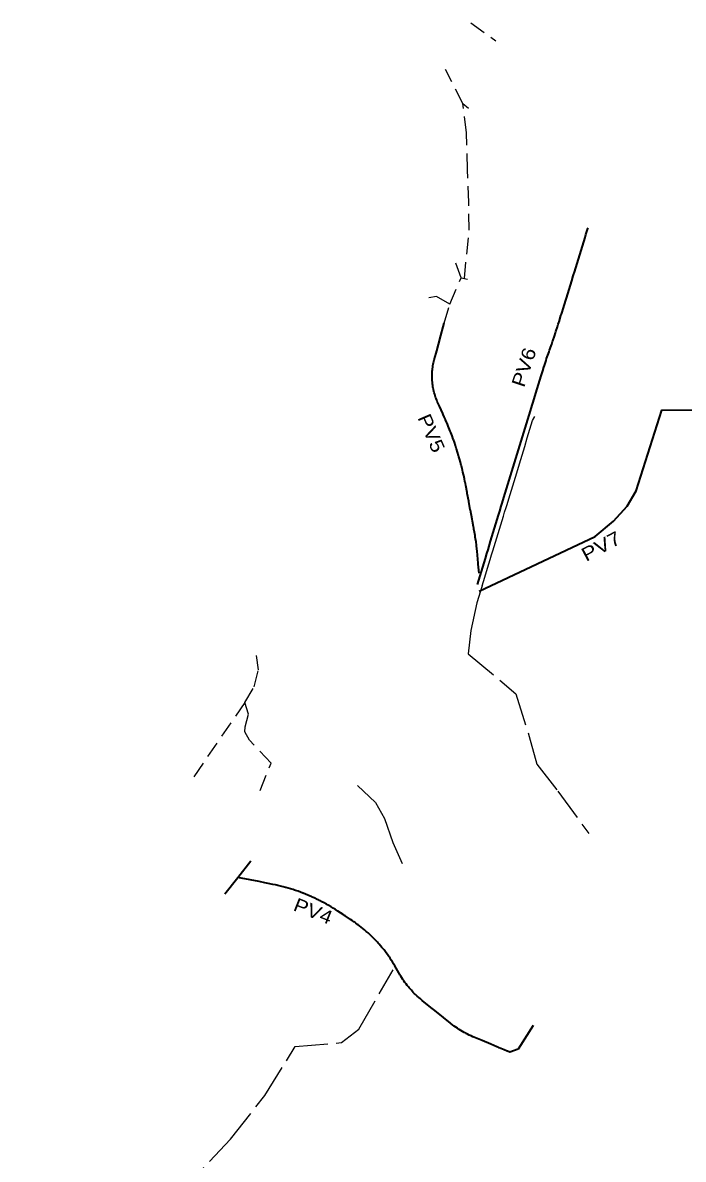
# Model space of a CAD drawing. Extents: x -509392 to -507242, y -1124532 to -1120864.
# Drawn here: x -509383 to -508657, y -1123277 to -1122027 of the extents above; entities that cross this region are included whole.
import ezdxf
from ezdxf.enums import TextEntityAlignment as Align

# ---------------------------------------------------------------- set-up
doc = ezdxf.new("R2010")
doc.units = 0
doc.header["$LTSCALE"] = 6
for name, pattern in [('DOT_DASHED', [7.7, 5, -1.2, 0.3, -1.2]), ('LONG_DASHED', [7.5, 6, -1.5]), ('MEDIUM_DASHED', [4.5, 3, -1.5])]:
    doc.linetypes.add(name, pattern=pattern)
for name, color, linetype, lineweight in [('1', 7, 'DOT_DASHED', 25), ('15', 7, 'Continuous', 35), ('3', 7, 'MEDIUM_DASHED', 25)]:
    doc.layers.add(name, color=color, linetype=linetype, lineweight=lineweight)

msp = doc.modelspace()

# ---------------------------------------------------------------- linework, layer by layer
at = {"layer": '1', "linetype": 'LONG_DASHED'}
for points in [[(-508877.773, -1122646.121), (-508874.854, -1122636.556), (-508871.935, -1122626.992), (-508869.016, -1122617.427), (-508867.394, -1122612.114), (-508866.097, -1122607.863), (-508863.178, -1122598.298), (-508860.259, -1122588.734), (-508857.34, -1122579.169), (-508854.421, -1122569.605), (-508853.124, -1122565.354), (-508851.502, -1122560.04), (-508850.475, -1122556.675), (-508848.583, -1122550.476), (-508845.664, -1122540.911), (-508842.745, -1122531.347), (-508839.826, -1122521.782), (-508836.907, -1122512.218), (-508833.988, -1122502.653), (-508831.069, -1122493.089), (-508828.15, -1122483.524), (-508825.231, -1122473.96), (-508822.312, -1122464.395), (-508820.002, -1122459.873)], [(-508877.773, -1122646.121), (-508883.737, -1122664.985), (-508890.195, -1122695.52), (-508893.028, -1122721.031)], [(-508893.028, -1122721.031), (-508840.728, -1122764.908), (-508826.05, -1122812.072), (-508817.598, -1122842.328), (-508794.468, -1122872.139), (-508760.662, -1122918.858)], [(-509382.968, -1123448.472), (-509269.518, -1123378.636), (-509154.613, -1123254.968), (-509116.796, -1123206.955), (-509083.343, -1123153.123), (-509032.436, -1123148.759), (-509013.527, -1123134.209), (-508975.71, -1123068.738)]]:
    msp.add_lwpolyline(points, dxfattribs=at)
at = {"layer": '1'}
msp.add_lwpolyline([(-509014.709, -1122865.783), (-508995.073, -1122884.697), (-508985.255, -1122902.156), (-508976.165, -1122928.708), (-508965.62, -1122951.623)], dxfattribs=at)
at = {"layer": '15'}
for points in [[(-508767.511, -1122272.402), (-508764.559, -1122262.847), (-508763.645, -1122259.89), (-508761.606, -1122253.293), (-508761.377, -1122252.55)], [(-508883.068, -1122644.869), (-508880.149, -1122635.304), (-508877.23, -1122625.74), (-508874.311, -1122616.175), (-508872.689, -1122610.861), (-508871.392, -1122606.611), (-508868.473, -1122597.046), (-508865.554, -1122587.482), (-508862.635, -1122577.917), (-508859.716, -1122568.353), (-508858.418, -1122564.102), (-508856.797, -1122558.788), (-508855.77, -1122555.423), (-508853.878, -1122549.224), (-508850.959, -1122539.659), (-508848.04, -1122530.095), (-508845.121, -1122520.53), (-508842.202, -1122510.966), (-508839.283, -1122501.401), (-508836.364, -1122491.837), (-508833.445, -1122482.272), (-508830.526, -1122472.708), (-508827.607, -1122463.143), (-508826.147, -1122458.361), (-508824.688, -1122453.579), (-508822.796, -1122447.379), (-508821.769, -1122444.014), (-508818.85, -1122434.45), (-508815.931, -1122424.885), (-508813.012, -1122415.321), (-508813.012, -1122415.321), (-508811.236, -1122409.589), (-508810.025, -1122405.777), (-508809.411, -1122403.873), (-508807.537, -1122398.173), (-508806.902, -1122396.278), (-508805.614, -1122392.489), (-508804.298, -1122388.689), (-508804.26, -1122388.581), (-508803.643, -1122386.824), (-508803.642, -1122386.821), (-508801.966, -1122382.068), (-508801.31, -1122380.2), (-508800.333, -1122377.387), (-508800.152, -1122376.862), (-508798.38, -1122371.641), (-508797.142, -1122367.91), (-508796.649, -1122366.407), (-508794.96, -1122361.159), (-508794.086, -1122358.389), (-508793.532, -1122356.611), (-508793.311, -1122355.898), (-508791.129, -1122348.836), (-508790.654, -1122347.299), (-508788.177, -1122339.282), (-508788.082, -1122338.973), (-508785.224, -1122329.727), (-508782.272, -1122320.173), (-508779.32, -1122310.619), (-508777.644, -1122305.194), (-508777.281, -1122304.022), (-508776.368, -1122301.065), (-508773.415, -1122291.51), (-508770.463, -1122281.956), (-508767.511, -1122272.402)], [(-508926.475, -1122444.887), (-508927.155, -1122443.356), (-508927.799, -1122441.81), (-508928.406, -1122440.248), (-508928.737, -1122439.346), (-508928.975, -1122438.673), (-508929.506, -1122437.084), (-508929.999, -1122435.484), (-508930.453, -1122433.871), (-508930.869, -1122432.249), (-508930.934, -1122431.98), (-508931.246, -1122430.617), (-508931.434, -1122429.725), (-508931.583, -1122428.976), (-508931.882, -1122427.328), (-508932.141, -1122425.673), (-508932.36, -1122424.012), (-508932.539, -1122422.347), (-508932.679, -1122420.677), (-508932.735, -1122419.819), (-508932.778, -1122419.005), (-508932.837, -1122417.331), (-508932.857, -1122415.656), (-508932.836, -1122413.982), (-508932.775, -1122412.308), (-508932.675, -1122410.636), (-508932.611, -1122409.828), (-508932.534, -1122408.967), (-508932.353, -1122407.301), (-508932.133, -1122405.641), (-508931.872, -1122403.986), (-508931.573, -1122402.338), (-508931.234, -1122400.698), (-508931.067, -1122399.957), (-508930.855, -1122399.066), (-508930.438, -1122397.444), (-508929.469, -1122393.853), (-508928.508, -1122390.29), (-508927.832, -1122387.789), (-508925.902, -1122380.636), (-508923.296, -1122370.981), (-508920.69, -1122361.327), (-508919.6, -1122357.288)], [(-508881.13, -1122632.399), (-508882.027, -1122622.439), (-508882.142, -1122621.16), (-508882.924, -1122612.479), (-508882.949, -1122612.196), (-508883.292, -1122608.63), (-508883.677, -1122605.067), (-508883.977, -1122602.536), (-508884.104, -1122601.51), (-508884.575, -1122597.958), (-508885.087, -1122594.411), (-508885.361, -1122592.632), (-508885.642, -1122590.872), (-508886.239, -1122587.339), (-508886.878, -1122583.813), (-508887.072, -1122582.78), (-508887.326, -1122581.427), (-508888.537, -1122574.967), (-508888.915, -1122572.951), (-508890.757, -1122563.123), (-508890.872, -1122562.51), (-508892.593, -1122553.335), (-508892.6, -1122553.294), (-508894.197, -1122544.775), (-508894.443, -1122543.465), (-508895.856, -1122535.929), (-508896.294, -1122533.638), (-508896.574, -1122532.212), (-508896.69, -1122531.635), (-508897.334, -1122528.502), (-508898.135, -1122524.802), (-508898.348, -1122523.852), (-508898.977, -1122521.11), (-508899.445, -1122519.139), (-508899.861, -1122517.429), (-508900.689, -1122514.13), (-508900.785, -1122513.757), (-508901.75, -1122510.096), (-508902.756, -1122506.445), (-508903.315, -1122504.481), (-508903.638, -1122503.365), (-508903.802, -1122502.806), (-508904.889, -1122499.179), (-508906.016, -1122495.565), (-508906.224, -1122494.914), (-508906.302, -1122494.67), (-508907.183, -1122491.963), (-508908.39, -1122488.374), (-508909.412, -1122485.436), (-508909.638, -1122484.799), (-508910.925, -1122481.239), (-508912.251, -1122477.692), (-508912.878, -1122476.057), (-508913.617, -1122474.161), (-508915.022, -1122470.645), (-508916.467, -1122467.145), (-508916.619, -1122466.783), (-508917.95, -1122463.661), (-508918.089, -1122463.34), (-508919.472, -1122460.194), (-508920.63, -1122457.623), (-508921.032, -1122456.745), (-508924.786, -1122448.565), (-508924.801, -1122448.534), (-508926.475, -1122444.887)], [(-508881.094, -1122652.194), (-508753.512, -1122591.89), (-508733.417, -1122575.061), (-508718.462, -1122558.7), (-508708.648, -1122541.871), (-508680.141, -1122453.052), (-508587.609, -1122452.584), (-508586.674, -1122485.307)], [(-509160.798, -1122985.283), (-509146.564, -1122967.046), (-509132.339, -1122948.651)], [(-509088.489, -1122979.611), (-509091.246, -1122978.789), (-509093.773, -1122978.074), (-509094.014, -1122978.008), (-509096.794, -1122977.266), (-509099.584, -1122976.565), (-509099.679, -1122976.541), (-509102.383, -1122975.903), (-509103.476, -1122975.657), (-509105.192, -1122975.282), (-509108.01, -1122974.702), (-509113.273, -1122973.656), (-509116.837, -1122972.949), (-509123.082, -1122971.709), (-509132.89, -1122969.761), (-509142.699, -1122967.813), (-509146.564, -1122967.046)], [(-508979.766, -1123054.988), (-508980.501, -1123053.921), (-508981.928, -1123051.906), (-508983.388, -1123049.914), (-508984.88, -1123047.947), (-508985.676, -1123046.924), (-508986.404, -1123046.004), (-508987.96, -1123044.087), (-508989.548, -1123042.196), (-508991.167, -1123040.332), (-508992.111, -1123039.271), (-508992.815, -1123038.494), (-508994.494, -1123036.683), (-508996.203, -1123034.901), (-508997.941, -1123033.146), (-508999.041, -1123032.065), (-508999.707, -1123031.421), (-509001.501, -1123029.725), (-509003.324, -1123028.059), (-509005.173, -1123026.423), (-509006.436, -1123025.336), (-509007.049, -1123024.817), (-509008.951, -1123023.243), (-509010.879, -1123021.7), (-509010.894, -1123021.688), (-509012.832, -1123020.189), (-509014.263, -1123019.114), (-509014.809, -1123018.711), (-509016.811, -1123017.265), (-509017.99, -1123016.436), (-509018.836, -1123015.852), (-509020.884, -1123014.473), (-509022.48, -1123013.418), (-509028.391, -1123009.508), (-509029.121, -1123009.025), (-509030.82, -1123007.901), (-509036.627, -1123004.06), (-509039.038, -1123002.491), (-509039.174, -1123002.404), (-509041.471, -1123000.956), (-509043.926, -1122999.456), (-509046.402, -1122997.992), (-509047.728, -1122997.227), (-509048.899, -1122996.563), (-509051.416, -1122995.171), (-509053.953, -1122993.815), (-509056.509, -1122992.495), (-509056.531, -1122992.484), (-509057.791, -1122991.851), (-509059.084, -1122991.213), (-509061.677, -1122989.967), (-509061.831, -1122989.895), (-509064.288, -1122988.759), (-509065.559, -1122988.187), (-509066.916, -1122987.589), (-509069.56, -1122986.457), (-509072.221, -1122985.362), (-509074.792, -1122984.347), (-509074.897, -1122984.307), (-509077.588, -1122983.289), (-509080.293, -1122982.311), (-509083.012, -1122981.372), (-509084.204, -1122980.973), (-509085.744, -1122980.471), (-509088.489, -1122979.611)], [(-508850.017, -1123158.338), (-508850.499, -1123158.124), (-508853.456, -1123156.851), (-508859.219, -1123154.424), (-508860.39, -1123153.931), (-508861.751, -1123153.358), (-508868.435, -1123150.543), (-508877.651, -1123146.661), (-508886.867, -1123142.78), (-508887.99, -1123142.307), (-508889.965, -1123141.45), (-508891.921, -1123140.551), (-508893.857, -1123139.609), (-508894.796, -1123139.135), (-508895.773, -1123138.627), (-508895.923, -1123138.548), (-508897.667, -1123137.603), (-508899.538, -1123136.539), (-508901.386, -1123135.435), (-508903.21, -1123134.291), (-508904.515, -1123133.439), (-508905.009, -1123133.109), (-508906.782, -1123131.887), (-508908.529, -1123130.628), (-508910.247, -1123129.332), (-508911.938, -1123127.999), (-508912.556, -1123127.501), (-508920.341, -1123121.225), (-508928.126, -1123114.949), (-508935.911, -1123108.672), (-508943.696, -1123102.396), (-508944.48, -1123101.764), (-508946.054, -1123100.469), (-508947.6, -1123099.142), (-508949.12, -1123097.784), (-508950.611, -1123096.396), (-508951.219, -1123095.813), (-508952.073, -1123094.977), (-508953.507, -1123093.528), (-508954.91, -1123092.051), (-508955.675, -1123091.221), (-508956.284, -1123090.546), (-508957.626, -1123089.012), (-508958.049, -1123088.515), (-508958.937, -1123087.452), (-508960.215, -1123085.866), (-508961.462, -1123084.253), (-508962.674, -1123082.616), (-508963.854, -1123080.954), (-508964.118, -1123080.572), (-508964.999, -1123079.269), (-508966.11, -1123077.56), (-508967.185, -1123075.829), (-508968.226, -1123074.077), (-508969.185, -1123072.422), (-508969.361, -1123072.12), (-508969.386, -1123072.076), (-508973.876, -1123064.334), (-508974.406, -1123063.427), (-508975.132, -1123062.208), (-508976.423, -1123060.104), (-508977.684, -1123058.119), (-508977.748, -1123058.02), (-508979.108, -1123055.959), (-508979.766, -1123054.988)], [(-508821.874, -1123130.019), (-508838.223, -1123155.985), (-508847.563, -1123159.445), (-508850.017, -1123158.338)]]:
    msp.add_lwpolyline(points, dxfattribs=at)
at = {"layer": '3'}
for p, q in [((-508890.214, -1122026.724), (-508862.919, -1122046.655)), ((-508898.948, -1122115.702), (-508892.943, -1122120.617)), ((-508900.931, -1122307.369), (-508893.888, -1122308.733)), ((-509138.893, -1122774.742), (-509196.485, -1122858.564))]:
    msp.add_line(p, q, dxfattribs=at)
for points in [[(-508897.41, -1122308.051), (-508892.133, -1122255.13), (-508892.406, -1122224.55), (-508893.77, -1122188.508), (-508894.862, -1122147.826), (-508898.948, -1122115.702), (-508918.055, -1122078.023)], [(-508919.6, -1122357.288), (-508913.429, -1122336.231), (-508900.931, -1122307.369), (-508906.839, -1122291.234)], [(-508913.429, -1122336.231), (-508928.198, -1122327.822), (-508936.378, -1122329.413)], [(-509121.97, -1122871.397), (-509109.96, -1122841.363), (-509133.707, -1122816.244), (-509138.62, -1122806.96), (-509138.347, -1122801.5), (-509134.799, -1122787.302), (-509138.893, -1122774.742), (-509128.521, -1122757.267), (-509123.881, -1122738.701), (-509125.791, -1122722.865)]]:
    msp.add_lwpolyline(points, dxfattribs=at)

# ---------------------------------------------------------------- texts
at = {"layer": '1'}
for s, rotation, width, p in [('PV6', 71.57, 1.15, (-508824.795, -1122408.16)), ('PV5', 293.379, 1.15, (-508940.517, -1122481.229)), ('PV7', 28.08, 1.2, (-508743.46, -1122609.336)), ('PV4', 338.171, 1.15, (-509066.404, -1123011.069))]:
    msp.add_text(s, height=15, rotation=rotation, dxfattribs=dict(at, width=width)).set_placement(p, align=Align.CENTER)

doc.saveas('drawing.dxf')
